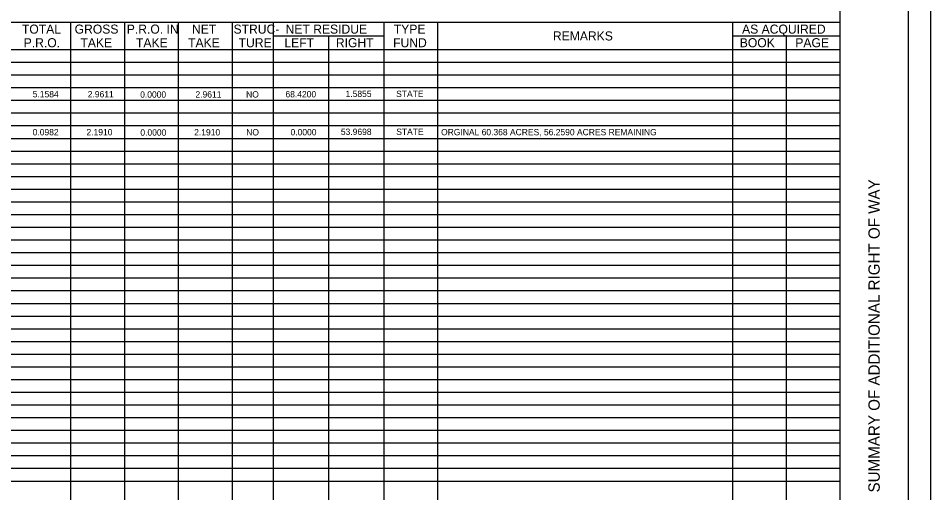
# Model space of a CAD drawing. Extents: x 0 to 34, y 0 to 30.9.
# Drawn here: x 13.88 to 34, y 9.68 to 20.15 of the extents above; entities that cross this region are included whole.
import ezdxf

# ---------------------------------------------------------------- set-up
doc = ezdxf.new("R2010")
doc.units = 0
for name, color, linetype in [('SH_Border', 7, 'Continuous'), ('SH_Cut_Line', 7, 'Continuous'), ('SH_Data', 7, 'Continuous'), ('SH_Text', 7, 'Continuous')]:
    doc.layers.add(name, color=color, linetype=linetype)

msp = doc.modelspace()

# ---------------------------------------------------------------- linework, layer by layer
at = {"layer": 'SH_Border'}
msp.add_line((32, 0.5), (32, 21.5), dxfattribs=at)
msp.add_lwpolyline([(1.5, 21.5), (33.5, 21.5), (33.5, 0.5), (1.5, 0.5)], close=True, dxfattribs=at)
at = {"layer": 'SH_Cut_Line'}
msp.add_lwpolyline([(0, 0), (34, 0), (34, 22), (0, 22)], close=True, dxfattribs=at)
at = {"layer": 'SH_Text'}
for p, q in [((1.5, 20.06), (32, 20.06)), ((15.031, 20.06), (15.031, 3.5)), ((16.219, 20.06), (16.219, 3.5)), ((17.406, 20.06), (17.406, 3.5)), ((18.594, 20.06), (18.594, 3.5)), ((19.5, 20.06), (19.5, 3.5)), ((21.937, 20.06), (21.937, 3.5)), ((23.125, 20.06), (23.125, 3.5)), ((29.625, 20.06), (29.625, 3.5)), ((19.5, 19.76), (21.937, 19.76)), ((20.719, 19.76), (20.719, 3.5)), ((29.625, 19.76), (32, 19.76)), ((30.812, 19.76), (30.812, 3.5)), ((1.5, 19.46), (32, 19.46)), ((1.5, 19.18), (32, 19.18)), ((1.5, 18.9), (32, 18.9)), ((1.5, 18.62), (32, 18.62)), ((1.5, 18.34), (32, 18.34)), ((1.5, 18.06), (32, 18.06)), ((1.5, 17.78), (32, 17.78)), ((1.5, 17.5), (32, 17.5)), ((1.5, 17.22), (32, 17.22)), ((1.5, 16.94), (32, 16.94)), ((1.5, 16.66), (32, 16.66)), ((1.5, 16.38), (32, 16.38)), ((1.5, 16.1), (32, 16.1)), ((1.5, 15.82), (32, 15.82)), ((1.5, 15.54), (32, 15.54)), ((1.5, 15.26), (32, 15.26)), ((1.5, 14.98), (32, 14.98)), ((1.5, 14.7), (32, 14.7)), ((1.5, 14.42), (32, 14.42)), ((1.5, 14.14), (32, 14.14)), ((1.5, 13.86), (32, 13.86)), ((1.5, 13.58), (32, 13.58)), ((1.5, 13.3), (32, 13.3)), ((1.5, 13.02), (32, 13.02)), ((1.5, 12.74), (32, 12.74)), ((1.5, 12.46), (32, 12.46)), ((1.5, 12.18), (32, 12.18)), ((1.5, 11.9), (32, 11.9)), ((1.5, 11.62), (32, 11.62)), ((1.5, 11.34), (32, 11.34)), ((1.5, 11.06), (32, 11.06)), ((1.5, 10.78), (32, 10.78)), ((1.5, 10.5), (32, 10.5)), ((1.5, 10.22), (32, 10.22)), ((1.5, 9.94), (32, 9.94))]:
    msp.add_line(p, q, dxfattribs=at)

# ---------------------------------------------------------------- texts
at = {"layer": 'SH_Data'}
msp.add_text('SUMMARY OF ADDITIONAL RIGHT OF WAY ', height=0.25, rotation=90, dxfattribs=at).set_placement((32.875, 9.687))
at = {"layer": 'SH_Text'}
for s, height, p in [('TOTAL', 0.2, (13.957, 19.81)), ('GROSS', 0.2, (15.119, 19.81)), ('P.R.O. IN', 0.2, (16.269, 19.81)), ('NET', 0.2, (17.707, 19.81)), ('STRUC-', 0.2, (18.624, 19.81)), ('NET RESIDUE', 0.2, (19.771, 19.81)), ('TYPE', 0.2, (22.158, 19.81)), ('AS ACQUIRED', 0.2, (29.839, 19.81)), ('REMARKS', 0.2, (25.667, 19.66)), ('P.R.O.', 0.2, (13.996, 19.51)), ('TAKE', 0.2, (15.247, 19.51)), ('TAKE', 0.2, (16.473, 19.51)), ('TAKE', 0.2, (17.622, 19.51)), ('TURE', 0.2, (18.736, 19.51)), ('LEFT', 0.2, (19.746, 19.51)), ('RIGHT', 0.2, (20.88, 19.51)), ('FUND', 0.2, (22.143, 19.51)), ('BOOK', 0.2, (29.788, 19.51)), ('PAGE', 0.2, (31.013, 19.51)), ('5.1584', 0.14, (14.195, 18.404)), ('2.9611', 0.14, (15.409, 18.404)), ('0.0000', 0.14, (16.565, 18.397)), ('2.9611', 0.14, (17.784, 18.4)), ('NO', 0.14, (18.901, 18.4)), ('68.4200', 0.14, (19.769, 18.404)), ('1.5855', 0.14, (21.095, 18.412)), ('STATE', 0.14, (22.21, 18.411)), ('0.0982', 0.14, (14.194, 17.567)), ('2.1910', 0.14, (15.381, 17.567)), ('0.0000', 0.14, (19.881, 17.567)), ('53.9698', 0.14, (20.991, 17.575)), ('STATE', 0.14, (22.213, 17.575)), ('ORGINAL 60.368 ACRES, 56.2590 ACRES REMAINING', 0.14, (23.201, 17.568)), ('0.0000', 0.14, (16.569, 17.56)), ('2.1910', 0.14, (17.756, 17.564)), ('NO', 0.14, (18.904, 17.564))]:
    msp.add_text(s, height=height, dxfattribs=at).set_placement(p)

doc.saveas('drawing.dxf')
